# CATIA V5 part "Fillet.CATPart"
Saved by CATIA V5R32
Part number: Part1
Bounding box of the stored display mesh (mm): x -37.5 to 37.5, y -94 to 94, z -94 to 94
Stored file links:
  D:\PROJECTS\Project 2022\CATIA V5 6R 2022\Resources\Part Files\c17_catia_v6_6r2022_prt\Fillet.CATPart
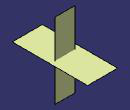
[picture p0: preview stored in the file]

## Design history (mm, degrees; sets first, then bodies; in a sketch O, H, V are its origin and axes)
Body1 (main body)
  Sketch1 on xy-plane, origin (0, 0, 0), H (1, 0, 0), V (0, 1, 0)
    line L1 (-25, 0) -> (25, 0)
    point P1 (-25, 0)
    point P2 (25, 0)
    length L1 = 50
    coincidence: P1 H
    horizontal: L1 H
    symmetry: P1 P2 V
  Sketch2 on zx-plane, origin (0, 0, 0), H (-1, 0, 0), V (0, 0, 1)
    line L1 (-37.5, 0) -> (37.5, 0)
    point P1 (-37.5, 0)
    point P2 (37.5, 0)
    length L1 = 75
    coincidence: P1 H
    horizontal: L1 H
    symmetry: P2 P1 V
  Extrude1: Element1 Sketch2, Lim1 94, Lim2 94
  Extrude2: Element1 Sketch1, Lim1 94, Lim2 94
